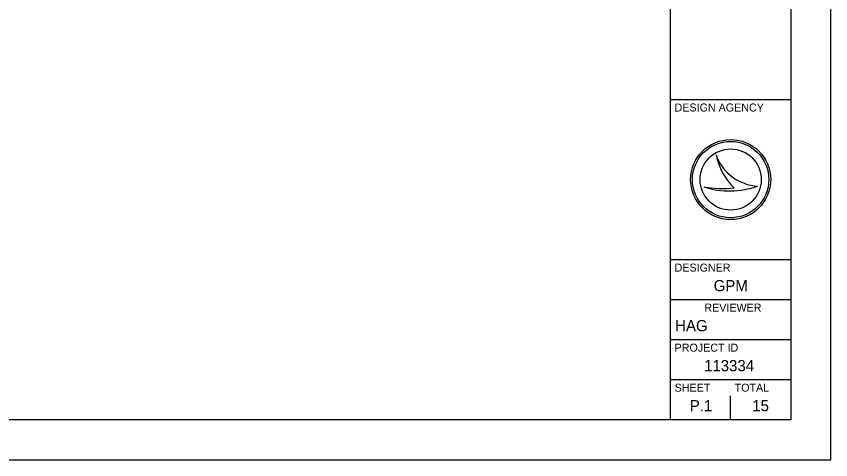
# Model space of a CAD drawing. Extents: x 0 to 34, y 0 to 22.
# Drawn here: x 23.83 to 34, y 0 to 5.54 of the extents above; entities that cross this region are included whole.
import ezdxf

# ---------------------------------------------------------------- set-up
doc = ezdxf.new("R2010")
doc.units = 0
for name, color, linetype in [('SH_Border', 7, 'Continuous'), ('SH_Cut_Line', 7, 'Continuous'), ('SH_Data', 7, 'Continuous')]:
    doc.layers.add(name, color=color, linetype=linetype)

msp = doc.modelspace()

# ---------------------------------------------------------------- linework, layer by layer
at = {"layer": 'SH_Border'}
for p, q in [((32, 0.5), (32, 21.5)), ((32, 4.5), (33.5, 4.5)), ((32, 2.5), (33.5, 2.5)), ((32, 2), (33.5, 2)), ((32, 1.5), (33.5, 1.5)), ((32, 1), (33.5, 1))]:
    msp.add_line(p, q, dxfattribs=at)
msp.add_lwpolyline([(1.5, 21.5), (33.5, 21.5), (33.5, 0.5), (1.5, 0.5)], close=True, dxfattribs=at)
at = {"layer": 'SH_Cut_Line'}
msp.add_lwpolyline([(0, 0), (34, 0), (34, 22), (0, 22)], close=True, dxfattribs=at)
at = {"layer": 'SH_Data'}
for p, q in [((32.567, 3.81), (32.567, 3.81)), ((32.75, 3.5), (32.75, 3.5)), ((32.417, 3.41), (32.417, 3.41)), ((33.087, 3.419), (33.087, 3.419)), ((32.75, 0.5), (32.75, 0.8)), ((32.375, 0.675), (32.375, 0.675))]:
    msp.add_line(p, q, dxfattribs=at)
for radius in [0.5, 0.477, 0.477, 0.382]:
    msp.add_circle((32.75, 3.5), radius, dxfattribs=at)
for centre, radius, start, end in [((33.116, 3.998), 0.58, 198.9257, 198.9319), ((33.347, 3.97), 0.796, 191.6379, 191.6421), ((33.116, 3.998), 0.58, 198.9319, 267.1657), ((33.347, 3.97), 0.796, 191.6421, 226.0947), ((32.739, 4.37), 1.013, 251.4576, 290.0832), ((32.648, 4.654), 1.266, 259.4964, 259.4995), ((32.739, 4.37), 1.013, 251.4527, 251.4576), ((32.648, 4.654), 1.266, 259.4995, 276.6672)]:
    msp.add_arc(centre, radius, start, end, dxfattribs=at)

# ---------------------------------------------------------------- texts
for s, height, p in [('DESIGN AGENCY', 0.1, (32.05, 4.35)), ('DESIGNER', 0.1, (32.05, 2.35)), ('GPM', 0.14, (32.538, 2.105)), ('REVIEWER', 0.1, (32.422, 1.85)), ('HAG', 0.14, (32.057, 1.605)), ('PROJECT ID', 0.1, (32.05, 1.35)), ('113334', 0.14, (32.418, 1.105)), ('SHEET', 0.1, (32.05, 0.85)), ('TOTAL', 0.1, (32.8, 0.85)), ('P.1', 0.14, (32.24, 0.605)), ('15', 0.14, (33.02, 0.605))]:
    msp.add_text(s, height=height, dxfattribs=at).set_placement(p)

doc.saveas('drawing.dxf')
